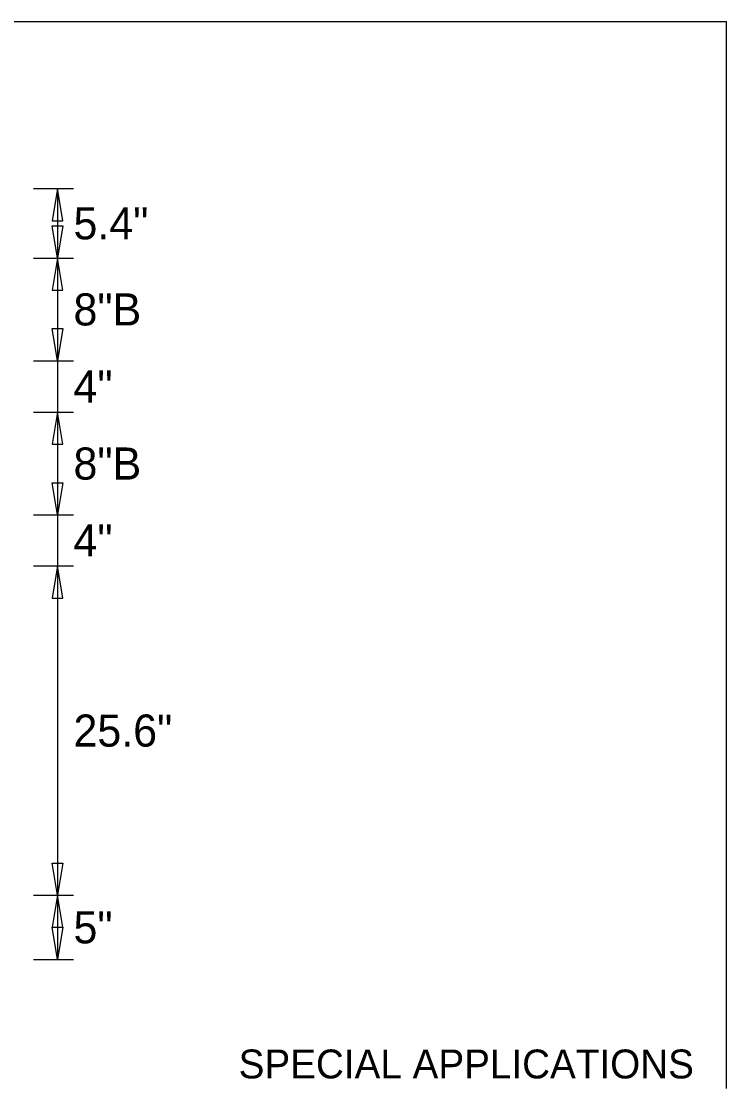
# Model space of a CAD drawing. Extents: x 17890628 to 17890844, y 17897693 to 17898031.
# Drawn here: x 17890757.27 to 17890771.91, y 17897934.95 to 17897957.11 of the extents above; entities that cross this region are included whole.
import ezdxf

# ---------------------------------------------------------------- set-up
doc = ezdxf.new("R2010")
doc.units = 0
doc.layers.add('GSDims', color=7, linetype='Continuous')
doc.layers.add('SheetLinesMisc2_dp', color=7, linetype='Continuous')

msp = doc.modelspace()

# ---------------------------------------------------------------- linework, layer by layer
at = {"layer": 'GSDims'}
for p, q in [((17890757.517, 17897953.637), (17890758.35, 17897953.637)), ((17890758.017, 17897953.637), (17890758.017, 17897952.197)), ((17890757.517, 17897952.197), (17890758.35, 17897952.197)), ((17890757.517, 17897952.197), (17890758.35, 17897952.197)), ((17890758.017, 17897952.197), (17890758.017, 17897950.064)), ((17890757.517, 17897950.064), (17890758.35, 17897950.064)), ((17890757.517, 17897950.064), (17890758.35, 17897950.064)), ((17890758.017, 17897950.064), (17890758.017, 17897948.997)), ((17890757.517, 17897948.997), (17890758.35, 17897948.997)), ((17890757.517, 17897948.997), (17890758.35, 17897948.997)), ((17890758.017, 17897948.997), (17890758.017, 17897946.864)), ((17890757.517, 17897946.864), (17890758.35, 17897946.864)), ((17890757.517, 17897946.864), (17890758.35, 17897946.864)), ((17890758.017, 17897946.864), (17890758.017, 17897945.805)), ((17890757.517, 17897945.805), (17890758.35, 17897945.805)), ((17890757.517, 17897945.805), (17890758.35, 17897945.805)), ((17890758.017, 17897945.805), (17890758.017, 17897938.97)), ((17890757.517, 17897938.97), (17890758.35, 17897938.97)), ((17890757.517, 17897938.97), (17890758.35, 17897938.97)), ((17890758.017, 17897938.97), (17890758.017, 17897937.637)), ((17890757.517, 17897937.637), (17890758.35, 17897937.637))]:
    msp.add_line(p, q, dxfattribs=at)
for points in [[(17890758.017, 17897953.637), (17890757.906, 17897952.971), (17890758.128, 17897952.971)], [(17890758.017, 17897952.197), (17890757.906, 17897952.864), (17890758.128, 17897952.864)], [(17890758.017, 17897952.197), (17890757.906, 17897951.531), (17890758.128, 17897951.531)], [(17890758.017, 17897950.064), (17890757.906, 17897950.731), (17890758.128, 17897950.731)], [(17890758.017, 17897948.997), (17890757.906, 17897948.331), (17890758.128, 17897948.331)], [(17890758.017, 17897946.864), (17890757.906, 17897947.531), (17890758.128, 17897947.531)], [(17890758.017, 17897945.805), (17890757.906, 17897945.138), (17890758.128, 17897945.138)], [(17890758.017, 17897938.97), (17890757.906, 17897939.637), (17890758.128, 17897939.637)], [(17890758.017, 17897938.97), (17890757.906, 17897938.304), (17890758.128, 17897938.304)], [(17890758.017, 17897937.637), (17890757.906, 17897938.304), (17890758.128, 17897938.304)]]:
    msp.add_lwpolyline(points, close=True, dxfattribs=at)
at = {"layer": 'SheetLinesMisc2_dp'}
for p, q in [((17890726.429, 17897957.108), (17890771.912, 17897957.108)), ((17890771.912, 17897934.985), (17890771.912, 17897957.109)), ((17890771.912, 17897934.955), (17890771.912, 17897934.985))]:
    msp.add_line(p, q, dxfattribs=at)

# ---------------------------------------------------------------- texts
at = {"layer": 'GSDims'}
for s, height, p in [('5.4"', 0.6667, (17890758.35, 17897952.584)), ('8"B', 0.6667, (17890758.35, 17897950.797)), ('4"', 0.6667, (17890758.35, 17897949.197)), ('8"B', 0.6667, (17890758.35, 17897947.597)), ('4"', 0.6667, (17890758.35, 17897946.001)), ('25.6"', 0.6667, (17890758.35, 17897942.054)), ('5"', 0.6667, (17890758.35, 17897937.97)), ('SPECIAL APPLICATIONS', 0.6, (17890761.779, 17897935.167))]:
    msp.add_text(s, height=height, dxfattribs=at).set_placement(p)

doc.saveas('drawing.dxf')
